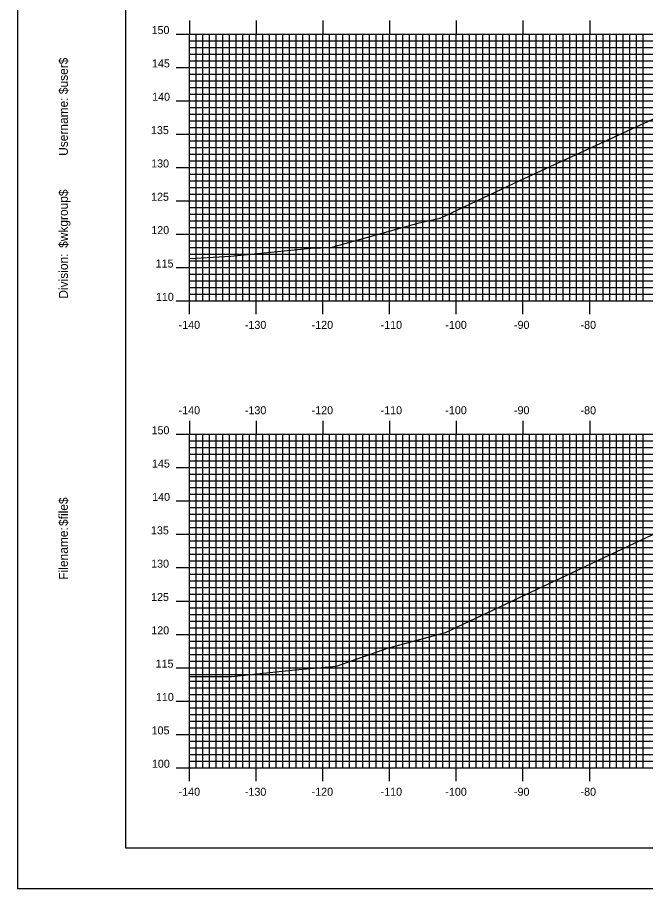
# Model space of a CAD drawing. Extents: x 860258 to 860601, y 364765 to 364985.
# Drawn here: x 860258.1 to 860352.3, y 364765.2 to 364895.8 of the extents above; entities that cross this region are included whole.
import ezdxf

# ---------------------------------------------------------------- set-up
doc = ezdxf.new("R2010")
doc.units = 0
for name, color, linetype in [('BORDER', 7, 'Continuous'), ('H_V ANNOTATION', 7, 'Continuous'), ('MAJOR', 7, 'Continuous'), ('MINOR', 7, 'Continuous'), ('PLOT BOUNDARY', 7, 'Continuous'), ('S_Roadway_Centerline', 7, 'Continuous')]:
    doc.layers.add(name, color=color, linetype=linetype)

msp = doc.modelspace()

# ---------------------------------------------------------------- linework, layer by layer
at = {"layer": 'BORDER'}
msp.add_lwpolyline([(860274.3, 364771.3), (860594.3, 364771.3), (860594.3, 364981.3), (860274.3, 364981.3)], close=True, dxfattribs=at)
at = {"layer": 'MAJOR'}
for p, q in [((860283.9, 364895.31), (860283.9, 364893.3)), ((860293.9, 364895.31), (860293.9, 364893.3)), ((860303.9, 364895.31), (860303.9, 364893.3)), ((860313.9, 364895.31), (860313.9, 364893.3)), ((860323.9, 364895.31), (860323.9, 364893.3)), ((860333.9, 364895.31), (860333.9, 364893.3)), ((860343.9, 364895.31), (860343.9, 364893.3)), ((860281.9, 364893.3), (860283.9, 364893.3)), ((860283.9, 364893.3), (860563.9, 364893.3)), ((860283.9, 364853.3), (860283.9, 364893.3)), ((860283.9, 364853.3), (860283.9, 364893.3)), ((860283.9, 364893.3), (860563.9, 364893.3)), ((860293.9, 364853.3), (860293.9, 364893.3)), ((860303.9, 364853.3), (860303.9, 364893.3)), ((860313.9, 364853.3), (860313.9, 364893.3)), ((860323.9, 364853.3), (860323.9, 364893.3)), ((860333.9, 364853.3), (860333.9, 364893.3)), ((860343.9, 364853.3), (860343.9, 364893.3)), ((860281.9, 364888.3), (860283.9, 364888.3)), ((860283.9, 364888.3), (860563.9, 364888.3)), ((860281.9, 364883.3), (860283.9, 364883.3)), ((860283.9, 364883.3), (860563.9, 364883.3)), ((860281.9, 364878.3), (860283.9, 364878.3)), ((860283.9, 364878.3), (860563.9, 364878.3)), ((860281.9, 364873.3), (860283.9, 364873.3)), ((860283.9, 364873.3), (860563.9, 364873.3)), ((860281.9, 364868.3), (860283.9, 364868.3)), ((860283.9, 364868.3), (860563.9, 364868.3)), ((860281.9, 364863.3), (860283.9, 364863.3)), ((860283.9, 364863.3), (860563.9, 364863.3)), ((860281.9, 364858.3), (860283.9, 364858.3)), ((860283.9, 364858.3), (860563.9, 364858.3)), ((860281.9, 364853.3), (860283.9, 364853.3)), ((860283.9, 364853.3), (860563.9, 364853.3)), ((860283.9, 364853.3), (860563.9, 364853.3)), ((860283.9, 364851.3), (860283.9, 364853.3)), ((860293.9, 364851.3), (860293.9, 364853.3)), ((860303.9, 364851.3), (860303.9, 364853.3)), ((860313.9, 364851.3), (860313.9, 364853.3)), ((860323.9, 364851.3), (860323.9, 364853.3)), ((860333.9, 364851.3), (860333.9, 364853.3)), ((860343.9, 364851.3), (860343.9, 364853.3)), ((860283.9, 364835.31), (860283.9, 364833.3)), ((860293.9, 364835.31), (860293.9, 364833.3)), ((860303.9, 364835.31), (860303.9, 364833.3)), ((860313.9, 364835.31), (860313.9, 364833.3)), ((860323.9, 364835.31), (860323.9, 364833.3)), ((860333.9, 364835.31), (860333.9, 364833.3)), ((860343.9, 364835.31), (860343.9, 364833.3)), ((860281.9, 364833.3), (860283.9, 364833.3)), ((860283.9, 364833.3), (860563.9, 364833.3)), ((860283.9, 364783.3), (860283.9, 364833.3)), ((860283.9, 364783.3), (860283.9, 364833.3)), ((860283.9, 364833.3), (860563.9, 364833.3)), ((860293.9, 364783.3), (860293.9, 364833.3)), ((860303.9, 364783.3), (860303.9, 364833.3)), ((860313.9, 364783.3), (860313.9, 364833.3)), ((860323.9, 364783.3), (860323.9, 364833.3)), ((860333.9, 364783.3), (860333.9, 364833.3)), ((860343.9, 364783.3), (860343.9, 364833.3)), ((860281.9, 364828.3), (860283.9, 364828.3)), ((860283.9, 364828.3), (860563.9, 364828.3)), ((860281.9, 364823.3), (860283.9, 364823.3)), ((860283.9, 364823.3), (860563.9, 364823.3)), ((860281.9, 364818.3), (860283.9, 364818.3)), ((860283.9, 364818.3), (860563.9, 364818.3)), ((860281.9, 364813.3), (860283.9, 364813.3)), ((860283.9, 364813.3), (860563.9, 364813.3)), ((860281.9, 364808.3), (860283.9, 364808.3)), ((860283.9, 364808.3), (860563.9, 364808.3)), ((860281.9, 364803.3), (860283.9, 364803.3)), ((860283.9, 364803.3), (860563.9, 364803.3)), ((860281.9, 364798.3), (860283.9, 364798.3)), ((860283.9, 364798.3), (860563.9, 364798.3)), ((860281.9, 364793.3), (860283.9, 364793.3)), ((860283.9, 364793.3), (860563.9, 364793.3)), ((860281.9, 364788.3), (860283.9, 364788.3)), ((860283.9, 364788.3), (860563.9, 364788.3)), ((860281.9, 364783.3), (860283.9, 364783.3)), ((860283.9, 364783.3), (860563.9, 364783.3)), ((860283.9, 364783.3), (860563.9, 364783.3)), ((860283.9, 364781.3), (860283.9, 364783.3)), ((860293.9, 364781.3), (860293.9, 364783.3)), ((860303.9, 364781.3), (860303.9, 364783.3)), ((860313.9, 364781.3), (860313.9, 364783.3)), ((860323.9, 364781.3), (860323.9, 364783.3)), ((860333.9, 364781.3), (860333.9, 364783.3)), ((860343.9, 364781.3), (860343.9, 364783.3))]:
    msp.add_line(p, q, dxfattribs=at)
at = {"layer": 'MINOR'}
for p, q in [((860284.9, 364853.3), (860284.9, 364893.3)), ((860285.9, 364853.3), (860285.9, 364893.3)), ((860286.9, 364853.3), (860286.9, 364893.3)), ((860287.9, 364853.3), (860287.9, 364893.3)), ((860288.9, 364853.3), (860288.9, 364893.3)), ((860289.9, 364853.3), (860289.9, 364893.3)), ((860290.9, 364853.3), (860290.9, 364893.3)), ((860291.9, 364853.3), (860291.9, 364893.3)), ((860292.9, 364853.3), (860292.9, 364893.3)), ((860294.9, 364853.3), (860294.9, 364893.3)), ((860295.9, 364853.3), (860295.9, 364893.3)), ((860296.9, 364853.3), (860296.9, 364893.3)), ((860297.9, 364853.3), (860297.9, 364893.3)), ((860298.9, 364853.3), (860298.9, 364893.3)), ((860299.9, 364853.3), (860299.9, 364893.3)), ((860300.9, 364853.3), (860300.9, 364893.3)), ((860301.9, 364853.3), (860301.9, 364893.3)), ((860302.9, 364853.3), (860302.9, 364893.3)), ((860304.9, 364853.3), (860304.9, 364893.3)), ((860305.9, 364853.3), (860305.9, 364893.3)), ((860306.9, 364853.3), (860306.9, 364893.3)), ((860307.9, 364853.3), (860307.9, 364893.3)), ((860308.9, 364853.3), (860308.9, 364893.3)), ((860309.9, 364853.3), (860309.9, 364893.3)), ((860310.9, 364853.3), (860310.9, 364893.3)), ((860311.9, 364853.3), (860311.9, 364893.3)), ((860312.9, 364853.3), (860312.9, 364893.3)), ((860314.9, 364853.3), (860314.9, 364893.3)), ((860315.9, 364853.3), (860315.9, 364893.3)), ((860316.9, 364853.3), (860316.9, 364893.3)), ((860317.9, 364853.3), (860317.9, 364893.3)), ((860318.9, 364853.3), (860318.9, 364893.3)), ((860319.9, 364853.3), (860319.9, 364893.3)), ((860320.9, 364853.3), (860320.9, 364893.3)), ((860321.9, 364853.3), (860321.9, 364893.3)), ((860322.9, 364853.3), (860322.9, 364893.3)), ((860324.9, 364853.3), (860324.9, 364893.3)), ((860325.9, 364853.3), (860325.9, 364893.3)), ((860326.9, 364853.3), (860326.9, 364893.3)), ((860327.9, 364853.3), (860327.9, 364893.3)), ((860328.9, 364853.3), (860328.9, 364893.3)), ((860329.9, 364853.3), (860329.9, 364893.3)), ((860330.9, 364853.3), (860330.9, 364893.3)), ((860331.9, 364853.3), (860331.9, 364893.3)), ((860332.9, 364853.3), (860332.9, 364893.3)), ((860334.9, 364853.3), (860334.9, 364893.3)), ((860335.9, 364853.3), (860335.9, 364893.3)), ((860336.9, 364853.3), (860336.9, 364893.3)), ((860337.9, 364853.3), (860337.9, 364893.3)), ((860338.9, 364853.3), (860338.9, 364893.3)), ((860339.9, 364853.3), (860339.9, 364893.3)), ((860340.9, 364853.3), (860340.9, 364893.3)), ((860341.9, 364853.3), (860341.9, 364893.3)), ((860342.9, 364853.3), (860342.9, 364893.3)), ((860344.9, 364853.3), (860344.9, 364893.3)), ((860345.9, 364853.3), (860345.9, 364893.3)), ((860346.9, 364853.3), (860346.9, 364893.3)), ((860347.9, 364853.3), (860347.9, 364893.3)), ((860348.9, 364853.3), (860348.9, 364893.3)), ((860349.9, 364853.3), (860349.9, 364893.3)), ((860350.9, 364853.3), (860350.9, 364893.3)), ((860351.9, 364853.3), (860351.9, 364893.3)), ((860283.9, 364892.3), (860563.9, 364892.3)), ((860283.9, 364892.3), (860285.9, 364892.3)), ((860283.9, 364891.3), (860563.9, 364891.3)), ((860283.9, 364891.3), (860285.9, 364891.3)), ((860283.9, 364890.3), (860563.9, 364890.3)), ((860283.9, 364890.3), (860285.9, 364890.3)), ((860283.9, 364889.3), (860563.9, 364889.3)), ((860283.9, 364889.3), (860285.9, 364889.3)), ((860283.9, 364887.3), (860563.9, 364887.3)), ((860283.9, 364887.3), (860285.9, 364887.3)), ((860283.9, 364886.3), (860563.9, 364886.3)), ((860283.9, 364886.3), (860285.9, 364886.3)), ((860283.9, 364885.3), (860563.9, 364885.3)), ((860283.9, 364885.3), (860285.9, 364885.3)), ((860283.9, 364884.3), (860563.9, 364884.3)), ((860283.9, 364884.3), (860285.9, 364884.3)), ((860283.9, 364882.3), (860563.9, 364882.3)), ((860283.9, 364882.3), (860285.9, 364882.3)), ((860283.9, 364881.3), (860563.9, 364881.3)), ((860283.9, 364881.3), (860285.9, 364881.3)), ((860283.9, 364880.3), (860563.9, 364880.3)), ((860283.9, 364880.3), (860285.9, 364880.3)), ((860283.9, 364879.3), (860563.9, 364879.3)), ((860283.9, 364879.3), (860285.9, 364879.3)), ((860283.9, 364877.3), (860563.9, 364877.3)), ((860283.9, 364877.3), (860285.9, 364877.3)), ((860283.9, 364876.3), (860563.9, 364876.3)), ((860283.9, 364876.3), (860285.9, 364876.3)), ((860283.9, 364875.3), (860563.9, 364875.3)), ((860283.9, 364875.3), (860285.9, 364875.3)), ((860283.9, 364874.3), (860563.9, 364874.3)), ((860283.9, 364874.3), (860285.9, 364874.3)), ((860283.9, 364872.3), (860563.9, 364872.3)), ((860283.9, 364872.3), (860285.9, 364872.3)), ((860283.9, 364871.3), (860563.9, 364871.3)), ((860283.9, 364871.3), (860285.9, 364871.3)), ((860283.9, 364870.3), (860563.9, 364870.3)), ((860283.9, 364870.3), (860285.9, 364870.3)), ((860283.9, 364869.3), (860563.9, 364869.3)), ((860283.9, 364869.3), (860285.9, 364869.3)), ((860283.9, 364867.3), (860563.9, 364867.3)), ((860283.9, 364867.3), (860285.9, 364867.3)), ((860283.9, 364866.3), (860563.9, 364866.3)), ((860283.9, 364866.3), (860285.9, 364866.3)), ((860283.9, 364865.3), (860563.9, 364865.3)), ((860283.9, 364865.3), (860285.9, 364865.3)), ((860283.9, 364864.3), (860563.9, 364864.3)), ((860283.9, 364864.3), (860285.9, 364864.3)), ((860283.9, 364862.3), (860563.9, 364862.3)), ((860283.9, 364862.3), (860285.9, 364862.3)), ((860283.9, 364861.3), (860563.9, 364861.3)), ((860283.9, 364861.3), (860285.9, 364861.3)), ((860283.9, 364860.3), (860563.9, 364860.3)), ((860283.9, 364860.3), (860285.9, 364860.3)), ((860283.9, 364859.3), (860563.9, 364859.3)), ((860283.9, 364859.3), (860285.9, 364859.3)), ((860283.9, 364857.3), (860563.9, 364857.3)), ((860283.9, 364857.3), (860285.9, 364857.3)), ((860283.9, 364856.3), (860563.9, 364856.3)), ((860283.9, 364856.3), (860285.9, 364856.3)), ((860283.9, 364855.3), (860563.9, 364855.3)), ((860283.9, 364855.3), (860285.9, 364855.3)), ((860283.9, 364854.3), (860563.9, 364854.3)), ((860283.9, 364854.3), (860285.9, 364854.3)), ((860284.9, 364783.3), (860284.9, 364833.3)), ((860285.9, 364783.3), (860285.9, 364833.3)), ((860286.9, 364783.3), (860286.9, 364833.3)), ((860287.9, 364783.3), (860287.9, 364833.3)), ((860288.9, 364783.3), (860288.9, 364833.3)), ((860289.9, 364783.3), (860289.9, 364833.3)), ((860290.9, 364783.3), (860290.9, 364833.3)), ((860291.9, 364783.3), (860291.9, 364833.3)), ((860292.9, 364783.3), (860292.9, 364833.3)), ((860294.9, 364783.3), (860294.9, 364833.3)), ((860295.9, 364783.3), (860295.9, 364833.3)), ((860296.9, 364783.3), (860296.9, 364833.3)), ((860297.9, 364783.3), (860297.9, 364833.3)), ((860298.9, 364783.3), (860298.9, 364833.3)), ((860299.9, 364783.3), (860299.9, 364833.3)), ((860300.9, 364783.3), (860300.9, 364833.3)), ((860301.9, 364783.3), (860301.9, 364833.3)), ((860302.9, 364783.3), (860302.9, 364833.3)), ((860304.9, 364783.3), (860304.9, 364833.3)), ((860305.9, 364783.3), (860305.9, 364833.3)), ((860306.9, 364783.3), (860306.9, 364833.3)), ((860307.9, 364783.3), (860307.9, 364833.3)), ((860308.9, 364783.3), (860308.9, 364833.3)), ((860309.9, 364783.3), (860309.9, 364833.3)), ((860310.9, 364783.3), (860310.9, 364833.3)), ((860311.9, 364783.3), (860311.9, 364833.3)), ((860312.9, 364783.3), (860312.9, 364833.3)), ((860314.9, 364783.3), (860314.9, 364833.3)), ((860315.9, 364783.3), (860315.9, 364833.3)), ((860316.9, 364783.3), (860316.9, 364833.3)), ((860317.9, 364783.3), (860317.9, 364833.3)), ((860318.9, 364783.3), (860318.9, 364833.3)), ((860319.9, 364783.3), (860319.9, 364833.3)), ((860320.9, 364783.3), (860320.9, 364833.3)), ((860321.9, 364783.3), (860321.9, 364833.3)), ((860322.9, 364783.3), (860322.9, 364833.3)), ((860324.9, 364783.3), (860324.9, 364833.3)), ((860325.9, 364783.3), (860325.9, 364833.3)), ((860326.9, 364783.3), (860326.9, 364833.3)), ((860327.9, 364783.3), (860327.9, 364833.3)), ((860328.9, 364783.3), (860328.9, 364833.3)), ((860329.9, 364783.3), (860329.9, 364833.3)), ((860330.9, 364783.3), (860330.9, 364833.3)), ((860331.9, 364783.3), (860331.9, 364833.3)), ((860332.9, 364783.3), (860332.9, 364833.3)), ((860334.9, 364783.3), (860334.9, 364833.3)), ((860335.9, 364783.3), (860335.9, 364833.3)), ((860336.9, 364783.3), (860336.9, 364833.3)), ((860337.9, 364783.3), (860337.9, 364833.3)), ((860338.9, 364783.3), (860338.9, 364833.3)), ((860339.9, 364783.3), (860339.9, 364833.3)), ((860340.9, 364783.3), (860340.9, 364833.3)), ((860341.9, 364783.3), (860341.9, 364833.3)), ((860342.9, 364783.3), (860342.9, 364833.3)), ((860344.9, 364783.3), (860344.9, 364833.3)), ((860345.9, 364783.3), (860345.9, 364833.3)), ((860346.9, 364783.3), (860346.9, 364833.3)), ((860347.9, 364783.3), (860347.9, 364833.3)), ((860348.9, 364783.3), (860348.9, 364833.3)), ((860349.9, 364783.3), (860349.9, 364833.3)), ((860350.9, 364783.3), (860350.9, 364833.3)), ((860351.9, 364783.3), (860351.9, 364833.3)), ((860283.9, 364832.3), (860563.9, 364832.3)), ((860283.9, 364832.3), (860285.9, 364832.3)), ((860283.9, 364831.3), (860563.9, 364831.3)), ((860283.9, 364831.3), (860285.9, 364831.3)), ((860283.9, 364830.3), (860563.9, 364830.3)), ((860283.9, 364830.3), (860285.9, 364830.3)), ((860283.9, 364829.3), (860563.9, 364829.3)), ((860283.9, 364829.3), (860285.9, 364829.3)), ((860283.9, 364827.3), (860563.9, 364827.3)), ((860283.9, 364827.3), (860285.9, 364827.3)), ((860283.9, 364826.3), (860563.9, 364826.3)), ((860283.9, 364826.3), (860285.9, 364826.3)), ((860283.9, 364825.3), (860563.9, 364825.3)), ((860283.9, 364825.3), (860285.9, 364825.3)), ((860283.9, 364824.3), (860563.9, 364824.3)), ((860283.9, 364824.3), (860285.9, 364824.3)), ((860283.9, 364822.3), (860563.9, 364822.3)), ((860283.9, 364822.3), (860285.9, 364822.3)), ((860283.9, 364821.3), (860563.9, 364821.3)), ((860283.9, 364821.3), (860285.9, 364821.3)), ((860283.9, 364820.3), (860563.9, 364820.3)), ((860283.9, 364820.3), (860285.9, 364820.3)), ((860283.9, 364819.3), (860563.9, 364819.3)), ((860283.9, 364819.3), (860285.9, 364819.3)), ((860283.9, 364817.3), (860563.9, 364817.3)), ((860283.9, 364817.3), (860285.9, 364817.3)), ((860283.9, 364816.3), (860563.9, 364816.3)), ((860283.9, 364816.3), (860285.9, 364816.3)), ((860283.9, 364815.3), (860563.9, 364815.3)), ((860283.9, 364815.3), (860285.9, 364815.3)), ((860283.9, 364814.3), (860563.9, 364814.3)), ((860283.9, 364814.3), (860285.9, 364814.3)), ((860283.9, 364812.3), (860563.9, 364812.3)), ((860283.9, 364812.3), (860285.9, 364812.3)), ((860283.9, 364811.3), (860563.9, 364811.3)), ((860283.9, 364811.3), (860285.9, 364811.3)), ((860283.9, 364810.3), (860563.9, 364810.3)), ((860283.9, 364810.3), (860285.9, 364810.3)), ((860283.9, 364809.3), (860563.9, 364809.3)), ((860283.9, 364809.3), (860285.9, 364809.3)), ((860283.9, 364807.3), (860563.9, 364807.3)), ((860283.9, 364807.3), (860285.9, 364807.3)), ((860283.9, 364806.3), (860563.9, 364806.3)), ((860283.9, 364806.3), (860285.9, 364806.3)), ((860283.9, 364805.3), (860563.9, 364805.3)), ((860283.9, 364805.3), (860285.9, 364805.3)), ((860283.9, 364804.3), (860563.9, 364804.3)), ((860283.9, 364804.3), (860285.9, 364804.3)), ((860283.9, 364802.3), (860563.9, 364802.3)), ((860283.9, 364802.3), (860285.9, 364802.3)), ((860283.9, 364801.3), (860563.9, 364801.3)), ((860283.9, 364801.3), (860285.9, 364801.3)), ((860283.9, 364800.3), (860563.9, 364800.3)), ((860283.9, 364800.3), (860285.9, 364800.3)), ((860283.9, 364799.3), (860563.9, 364799.3)), ((860283.9, 364799.3), (860285.9, 364799.3)), ((860283.9, 364797.3), (860563.9, 364797.3)), ((860283.9, 364797.3), (860285.9, 364797.3)), ((860283.9, 364796.3), (860563.9, 364796.3)), ((860283.9, 364796.3), (860285.9, 364796.3)), ((860283.9, 364795.3), (860563.9, 364795.3)), ((860283.9, 364795.3), (860285.9, 364795.3)), ((860283.9, 364794.3), (860563.9, 364794.3)), ((860283.9, 364794.3), (860285.9, 364794.3)), ((860283.9, 364792.3), (860563.9, 364792.3)), ((860283.9, 364792.3), (860285.9, 364792.3)), ((860283.9, 364791.3), (860563.9, 364791.3)), ((860283.9, 364791.3), (860285.9, 364791.3)), ((860283.9, 364790.3), (860563.9, 364790.3)), ((860283.9, 364790.3), (860285.9, 364790.3)), ((860283.9, 364789.3), (860563.9, 364789.3)), ((860283.9, 364789.3), (860285.9, 364789.3)), ((860283.9, 364787.3), (860563.9, 364787.3)), ((860283.9, 364787.3), (860285.9, 364787.3)), ((860283.9, 364786.3), (860563.9, 364786.3)), ((860283.9, 364786.3), (860285.9, 364786.3)), ((860283.9, 364785.3), (860563.9, 364785.3)), ((860283.9, 364785.3), (860285.9, 364785.3)), ((860283.9, 364784.3), (860563.9, 364784.3)), ((860283.9, 364784.3), (860285.9, 364784.3))]:
    msp.add_line(p, q, dxfattribs=at)
at = {"layer": 'PLOT BOUNDARY'}
msp.add_lwpolyline([(860258.11, 364765.18), (860598.11, 364765.18), (860598.11, 364985.18), (860258.11, 364985.18)], close=True, dxfattribs=at)
at = {"layer": 'S_Roadway_Centerline'}
for points in [[(860283.9, 364859.67), (860290.09, 364860.01), (860302.08, 364861.18), (860305.08, 364861.32), (860318.33, 364864.99), (860321.46, 364865.71), (860333.43, 364871.36), (860361.72, 364884.4), (860363.88, 364884.54), (860380.1, 364885.75), (860404.19, 364886.47), (860411.74, 364886.71), (860418.65, 364886.91), (860432.09, 364887.3), (860483.02, 364864.87)], [(860283.9, 364796.96), (860290.18, 364796.96), (860299.75, 364797.98), (860305.93, 364798.53), (860313.61, 364801.22), (860322.26, 364803.6), (860358.85, 364820.88), (860361.69, 364822.24), (860363.15, 364822.34), (860380.66, 364823.52), (860399.27, 364824.1), (860412.09, 364824.44), (860420.65, 364824.63), (860432, 364824.89), (860461.6, 364810.79)]]:
    msp.add_lwpolyline(points, dxfattribs=at)

# ---------------------------------------------------------------- texts
at = {"layer": 'BORDER'}
for s, p in [('$user$', (860265.67, 364884.29)), ('Username:', (860265.67, 364875.04)), ('$wkgroup$', (860265.67, 364861.24)), ('Division:', (860265.67, 364853.63)), ('$file$', (860265.67, 364819.55)), ('Filename:', (860265.67, 364811.5))]:
    msp.add_text(s, height=1.339, rotation=90, dxfattribs=at).set_placement(p)
at = {"layer": 'H_V ANNOTATION'}
for s, p in [('150', (860278.22, 364893.3)), ('145', (860278.28, 364888.3)), ('140', (860278.31, 364883.3)), ('135', (860278.13, 364878.3)), ('130', (860278.16, 364873.3)), ('125', (860278.15, 364868.3)), ('120', (860278.18, 364863.3)), ('115', (860278.83, 364858.3)), ('110', (860278.87, 364853.3)), ('-140', (860282.28, 364849.1)), ('-130', (860292.21, 364849.1)), ('-120', (860302.22, 364849.1)), ('-110', (860312.56, 364849.1)), ('-100', (860322.26, 364849.1)), ('-90', (860332.55, 364849.1)), ('-80', (860342.53, 364849.1)), ('-140', (860282.28, 364836.3)), ('-130', (860292.21, 364836.3)), ('-120', (860302.22, 364836.3)), ('-110', (860312.56, 364836.3)), ('-100', (860322.26, 364836.3)), ('-90', (860332.55, 364836.3)), ('-80', (860342.53, 364836.3)), ('150', (860278.22, 364833.3)), ('145', (860278.28, 364828.3)), ('140', (860278.31, 364823.3)), ('135', (860278.13, 364818.3)), ('130', (860278.16, 364813.3)), ('125', (860278.15, 364808.3)), ('120', (860278.18, 364803.3)), ('115', (860278.83, 364798.3)), ('110', (860278.87, 364793.3)), ('105', (860278.23, 364788.3)), ('100', (860278.27, 364783.3)), ('-140', (860282.28, 364779.1)), ('-130', (860292.21, 364779.1)), ('-120', (860302.22, 364779.1)), ('-110', (860312.56, 364779.1)), ('-100', (860322.26, 364779.1)), ('-90', (860332.55, 364779.1)), ('-80', (860342.53, 364779.1))]:
    msp.add_text(s, height=1.2, dxfattribs=at).set_placement(p)
at = {"layer": 'MAJOR'}
for p in [(860283.89, 364853.3), (860283.89, 364783.3)]:
    msp.add_text('-', height=0.012, dxfattribs=at).set_placement(p)

doc.saveas('drawing.dxf')
